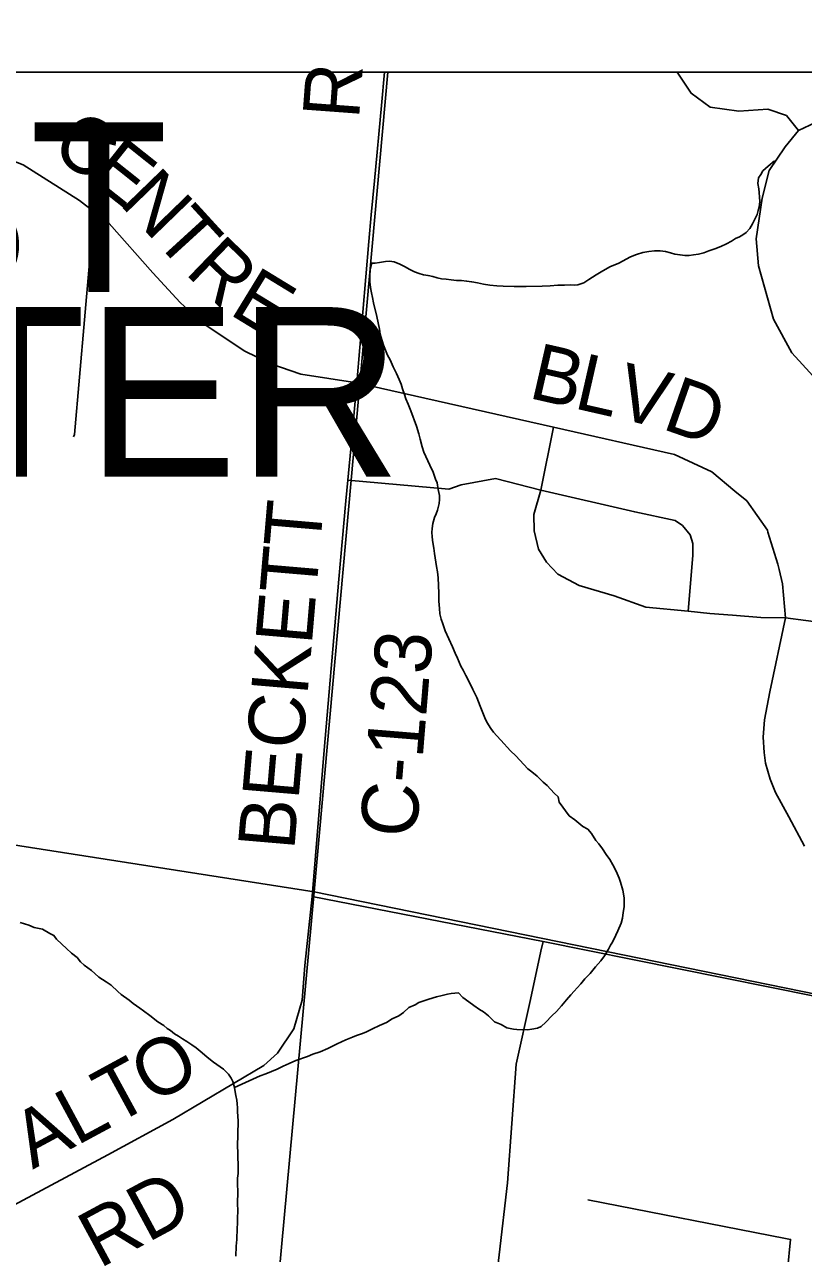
# Model space of a CAD drawing. Extents: x 0 to 34, y 0 to 22.
# Drawn here: x 5.283 to 6.065, y 16.973 to 18.207 of the extents above; entities that cross this region are included whole.
import ezdxf

# ---------------------------------------------------------------- set-up
doc = ezdxf.new("R2010")
doc.units = 0
for name, color, linetype in [('GM_X_County_Road', 7, 'Continuous'), ('GM_X_County_Road_Text', 7, 'Continuous'), ('GM_X_Minor_River', 7, 'Continuous'), ('GM_X_Section', 7, 'Continuous'), ('GM_X_Township_Road', 7, 'Continuous'), ('GM_X_Township_Road_Text', 7, 'Continuous'), ('GM_X_Township_Text', 7, 'Continuous'), ('SH_Text', 7, 'Continuous')]:
    doc.layers.add(name, color=color, linetype=linetype)

msp = doc.modelspace()

# ---------------------------------------------------------------- linework, layer by layer
at = {"layer": 'GM_X_County_Road'}
for p, q in [((5.6163, 17.8474), (5.6285, 17.9891)), ((5.6109, 17.788), (5.6163, 17.8474))]:
    msp.add_line(p, q, dxfattribs=at)
for points in [[(4.6846, 18.1624), (4.7517, 18.1578), (4.9233, 18.1379), (5.0879, 18.1139), (5.1086, 18.1108), (5.192, 18.0966), (5.238, 18.0831), (5.2814, 18.0662), (5.3381, 18.0304), (5.3678, 18.0072), (5.4117, 17.9578), (5.4392, 17.9278), (5.4607, 17.9078), (5.5032, 17.8793), (5.5302, 17.8663), (5.5602, 17.8558), (5.6163, 17.8474)], [(5.6341, 18.0503), (5.6413, 18.1257), (5.644, 18.1592)], [(5.6285, 17.9891), (5.6309, 18.0161), (5.6341, 18.0503)], [(5.6163, 17.8474), (5.8138, 17.8027), (5.9354, 17.7752), (5.9728, 17.7578), (5.996, 17.7384), (6.0079, 17.7286), (6.0285, 17.6991), (6.0291, 17.6973)], [(5.6055, 17.7286), (5.6074, 17.7495), (5.6109, 17.788)], [(5.5717, 17.3314), (5.5835, 17.4781), (5.5984, 17.6501), (5.6055, 17.7286)], [(6.0291, 17.6973), (6.0391, 17.6652), (6.0404, 17.6596)], [(6.0404, 17.6596), (6.0438, 17.6454), (6.0466, 17.6112)], [(6.0466, 17.6112), (6.031, 17.5368), (6.0255, 17.5088), (6.0243, 17.4913), (6.0252, 17.476), (6.0267, 17.4651), (6.0312, 17.4491), (6.0366, 17.4357), (6.05, 17.4113), (6.0658, 17.3817)], [(6.0466, 17.6112), (6.0876, 17.6058), (6.1121, 17.5959), (6.1422, 17.5721), (6.2262, 17.4703), (6.4637, 17.327), (6.5163, 17.296), (6.5237, 17.2912)], [(5.5717, 17.3314), (5.8034, 17.2861), (6.0757, 17.231)]]:
    msp.add_lwpolyline(points, dxfattribs=at)
at = {"layer": 'GM_X_Minor_River'}
for points in [[(5.7216, 17.9501), (5.7265, 17.9495), (5.7318, 17.9486), (5.7375, 17.9477), (5.7435, 17.9464), (5.75, 17.9454), (5.7568, 17.9448), (5.7632, 17.9442), (5.7743, 17.9439), (5.7796, 17.9441), (5.7864, 17.9439), (5.8024, 17.9442), (5.8104, 17.9447), (5.818, 17.9452), (5.8249, 17.9454), (5.8309, 17.9456), (5.8347, 17.9455), (5.8382, 17.9457), (5.8443, 17.9478), (5.8493, 17.9511), (5.8567, 17.9558), (5.8617, 17.9587), (5.8702, 17.9638), (5.8795, 17.9673), (5.8911, 17.9738), (5.8972, 17.9763), (5.9034, 17.9783), (5.9095, 17.9793), (5.9152, 17.9799), (5.9209, 17.9797), (5.9262, 17.9792), (5.9311, 17.9779), (5.9356, 17.9766), (5.9409, 17.9757), (5.9455, 17.9752), (5.95, 17.975), (5.9542, 17.9757), (5.9592, 17.9766), (5.9646, 17.978), (5.9699, 17.9797), (5.9757, 17.9818), (5.9818, 17.9843), (5.9876, 17.9868), (5.9926, 17.9897), (5.9965, 17.9922), (6.0004, 17.994), (6.0038, 17.9958), (6.0073, 17.9984), (6.0109, 18.0024), (6.0137, 18.0069), (6.0165, 18.0129), (6.0181, 18.0163), (6.0194, 18.0204), (6.0203, 18.0238), (6.0208, 18.0295), (6.0205, 18.0337), (6.0203, 18.0383), (6.02, 18.0421), (6.019, 18.0474), (6.0196, 18.0531), (6.022, 18.0565), (6.024, 18.0602), (6.0294, 18.065), (6.0357, 18.0701)], [(5.776, 17.4725), (5.7708, 17.4776), (5.7609, 17.4882), (5.7568, 17.4928), (5.7535, 17.4964), (5.7509, 17.4999), (5.747, 17.5064), (5.7448, 17.5107), (5.743, 17.5157), (5.7402, 17.5226), (5.7367, 17.5311), (5.7327, 17.5392), (5.7291, 17.5469), (5.7259, 17.5531), (5.723, 17.5585), (5.7209, 17.5627), (5.7191, 17.5666), (5.7173, 17.5708), (5.7152, 17.5758), (5.7123, 17.582), (5.7052, 17.5982), (5.7027, 17.6051), (5.701, 17.6097), (5.6996, 17.6151), (5.6994, 17.6204), (5.6988, 17.628), (5.6987, 17.636), (5.6982, 17.6436), (5.698, 17.6512), (5.6974, 17.6573), (5.6964, 17.6627), (5.6945, 17.6757), (5.6936, 17.681), (5.6929, 17.6849), (5.6923, 17.6891), (5.692, 17.6929), (5.6917, 17.697), (5.6919, 17.7008), (5.6928, 17.7061), (5.6945, 17.7118), (5.6961, 17.7155), (5.6973, 17.7193), (5.6991, 17.7261), (5.6995, 17.7299), (5.6993, 17.7341), (5.698, 17.7402), (5.697, 17.7467), (5.6952, 17.7505), (5.6931, 17.7574), (5.6895, 17.7644), (5.6838, 17.7775), (5.6821, 17.7829), (5.68, 17.7905), (5.6787, 17.7959), (5.6762, 17.8036), (5.6706, 17.819), (5.6678, 17.8259), (5.6657, 17.8313), (5.6643, 17.8355), (5.6621, 17.8413), (5.6608, 17.8459), (5.659, 17.8505), (5.6561, 17.8566), (5.6529, 17.8632), (5.6497, 17.8705), (5.6472, 17.8752), (5.6451, 17.8802), (5.6433, 17.8852), (5.6419, 17.8894), (5.6398, 17.8963), (5.6392, 17.9013), (5.6379, 17.9074), (5.6365, 17.9139), (5.6331, 17.9277), (5.6322, 17.933), (5.6312, 17.9376), (5.6305, 17.9411), (5.6299, 17.9456), (5.6296, 17.9491), (5.6294, 17.9548), (5.6299, 17.9608), (5.6313, 17.9673), (5.6347, 17.9675), (5.6393, 17.9682), (5.645, 17.9691), (5.6492, 17.9694), (5.6537, 17.9689), (5.6594, 17.9664), (5.6642, 17.964), (5.6695, 17.9612), (5.6743, 17.9587), (5.6789, 17.9571), (5.6834, 17.9558), (5.6879, 17.9549), (5.6928, 17.954), (5.697, 17.9527), (5.7015, 17.9518), (5.7061, 17.9513), (5.711, 17.9508), (5.7163, 17.9502), (5.7216, 17.9501)], [(5.4937, 17.1393), (5.5195, 17.1511), (5.5249, 17.1532), (5.5306, 17.1553), (5.5364, 17.1578), (5.5426, 17.1607), (5.5484, 17.1635), (5.5553, 17.1664), (5.5668, 17.1706), (5.5722, 17.1727), (5.5795, 17.1751), (5.5872, 17.1787), (5.5968, 17.1833), (5.6053, 17.1873), (5.6122, 17.1901), (5.6161, 17.1915), (5.6211, 17.1933), (5.6253, 17.195), (5.6322, 17.1982), (5.6392, 17.2018), (5.6461, 17.2047), (5.6519, 17.2083), (5.6585, 17.2115), (5.6631, 17.2148), (5.6686, 17.2196), (5.6748, 17.2224), (5.6786, 17.2246), (5.6886, 17.2281), (5.6963, 17.2305), (5.702, 17.2318), (5.7074, 17.2332), (5.7112, 17.2338), (5.7146, 17.2341), (5.7184, 17.2344), (5.7229, 17.2297), (5.7288, 17.2253), (5.734, 17.2217), (5.7396, 17.2178), (5.7437, 17.2154), (5.7486, 17.2114), (5.7545, 17.2055), (5.7612, 17.2027), (5.7668, 17.1994), (5.7736, 17.1981), (5.777, 17.1976), (5.7877, 17.1973), (5.7919, 17.1979), (5.7976, 17.1989), (5.8015, 17.2007), (5.8061, 17.2051), (5.812, 17.2114), (5.8167, 17.2158), (5.8218, 17.2213), (5.827, 17.2276), (5.8313, 17.2325), (5.8344, 17.2362), (5.8376, 17.2395), (5.8411, 17.2436), (5.8454, 17.2484), (5.8505, 17.2539), (5.856, 17.2606), (5.8612, 17.2665), (5.8651, 17.2717), (5.8691, 17.2784), (5.8711, 17.2822), (5.8731, 17.2855), (5.8764, 17.2923), (5.8784, 17.2968), (5.8817, 17.3043), (5.883, 17.3096), (5.8839, 17.3152), (5.8848, 17.3209), (5.8849, 17.3251), (5.8847, 17.3297), (5.884, 17.3339), (5.8834, 17.3377), (5.881, 17.3457), (5.8796, 17.3496), (5.8778, 17.3542), (5.8757, 17.3588), (5.8735, 17.3631), (5.8702, 17.3685), (5.8666, 17.3735), (5.8629, 17.379), (5.8593, 17.384), (5.8564, 17.3875), (5.852, 17.3945), (5.8483, 17.3988), (5.8431, 17.4016), (5.8353, 17.4083), (5.8297, 17.4123), (5.8195, 17.4259), (5.8185, 17.4313), (5.8144, 17.4352), (5.8074, 17.4426), (5.8033, 17.4462), (5.7974, 17.4521), (5.7919, 17.4564), (5.7881, 17.4596), (5.78, 17.4682), (5.776, 17.4725)], [(5.4948, 16.97), (5.4953, 16.9799), (5.4959, 16.9867), (5.4959, 16.9901), (5.4964, 16.9947), (5.4969, 17.0175), (5.4966, 17.0209), (5.4969, 17.0365), (5.4966, 17.0407), (5.4967, 17.0445), (5.4967, 17.0483), (5.4972, 17.0529), (5.4974, 17.0628), (5.4968, 17.0685), (5.4969, 17.0746), (5.4966, 17.0799), (5.4971, 17.1054), (5.4966, 17.1153), (5.4967, 17.1191), (5.4964, 17.1229), (5.496, 17.1267), (5.495, 17.1313), (5.4943, 17.1351), (5.4937, 17.1393), (5.4919, 17.1454), (5.4901, 17.1489), (5.4875, 17.1527), (5.4827, 17.1578), (5.4726, 17.1648), (5.4663, 17.1699), (5.4611, 17.1742), (5.4551, 17.1793), (5.4507, 17.1824), (5.4458, 17.1855), (5.4413, 17.1883), (5.4372, 17.191), (5.4335, 17.1934), (5.4294, 17.1965), (5.426, 17.1985), (5.4227, 17.2016), (5.4167, 17.2055), (5.4085, 17.2118), (5.4022, 17.2165), (5.3985, 17.2189), (5.3918, 17.2236), (5.3877, 17.2271), (5.3799, 17.2329), (5.3765, 17.2357), (5.3698, 17.2423), (5.3646, 17.2454), (5.3575, 17.2501), (5.3534, 17.254), (5.3501, 17.2568), (5.3426, 17.2622), (5.3389, 17.2657), (5.3356, 17.27), (5.33, 17.2743), (5.3248, 17.279), (5.3204, 17.2832), (5.3148, 17.2883), (5.3123, 17.2922), (5.3081, 17.2941), (5.301, 17.2985), (5.2924, 17.3002), (5.2871, 17.3026), (5.2785, 17.305)]]:
    msp.add_lwpolyline(points, dxfattribs=at)
at = {"layer": 'GM_X_Section'}
for points in [[(5.6474, 18.1592), (5.5736, 17.336), (4.5906, 17.4897), (4.6831, 18.5192), (5.1102, 18.4472)], [(6.5636, 18.1592), (6.6692, 18.1363), (6.585, 17.1294), (5.5736, 17.336), (5.6474, 18.1592)], [(4.8773, 16.3947), (4.4981, 16.447), (4.5906, 17.4897), (5.5736, 17.336), (5.489, 16.4145)], [(5.489, 16.4145), (5.5736, 17.336), (6.585, 17.1294), (6.5225, 16.4145)]]:
    msp.add_lwpolyline(points, dxfattribs=at)
at = {"layer": 'GM_X_Township_Road'}
for p, q in [((5.8012, 17.2763), (5.8034, 17.2861)), ((5.7906, 17.2278), (5.8012, 17.2763)), ((6.0466, 16.9877), (5.8483, 17.0266))]:
    msp.add_line(p, q, dxfattribs=at)
for points in [[(6.0597, 18.1006), (6.0476, 18.1158), (6.0288, 18.1223), (5.9997, 18.12), (5.9711, 18.1242), (5.9519, 18.1381), (5.9379, 18.1592)], [(6.0815, 17.8463), (6.0531, 17.8775), (6.0348, 17.9113), (6.0196, 17.9648), (6.0172, 17.992), (6.0233, 18.0327), (6.0303, 18.0605), (6.0463, 18.0843), (6.0597, 18.1006), (6.1111, 18.1247)], [(5.3319, 17.7931), (5.3328, 17.7952), (5.3479, 17.968), (5.3481, 17.9695), (5.3486, 17.9725), (5.3492, 17.9752), (5.3499, 17.9779), (5.3506, 17.9802), (5.3515, 17.9825), (5.3525, 17.9851), (5.3537, 17.9876), (5.355, 17.9904), (5.3563, 17.9925), (5.3579, 17.9951), (5.3592, 17.9971), (5.3614, 17.9999), (5.3641, 18.0031), (5.3678, 18.0072)], [(5.8138, 17.8027), (5.8012, 17.7395), (5.7939, 17.7151), (5.7944, 17.6985), (5.7987, 17.6802), (5.8069, 17.6672), (5.8183, 17.655), (5.8395, 17.6435), (5.8746, 17.6332), (5.9064, 17.6218), (5.9489, 17.618), (5.9709, 17.6155), (5.9935, 17.6139), (6.022, 17.6115), (6.0466, 17.6112)], [(5.6074, 17.7495), (5.7089, 17.7405), (5.721, 17.7447), (5.7556, 17.751), (5.8012, 17.7395), (5.8953, 17.7175), (5.9358, 17.7088), (5.9434, 17.7039), (5.951, 17.6947), (5.9538, 17.6857), (5.9538, 17.6737), (5.9489, 17.618)], [(5.1782, 16.9728), (5.2241, 16.9957), (5.3665, 17.0716), (5.4316, 17.1072), (5.5229, 17.1614), (5.5369, 17.1739), (5.5533, 17.1982), (5.5614, 17.2271), (5.5641, 17.262), (5.5717, 17.3314)], [(5.9884, 16.7109), (5.9765, 16.7119), (5.7564, 16.761), (5.7473, 16.7687), (5.7375, 16.7841), (5.7319, 16.8114), (5.7389, 16.8486), (5.7508, 16.8991), (5.7676, 17.0435), (5.7764, 17.1627), (5.7906, 17.2278)], [(6.062, 16.8517), (6.0504, 16.8591), (6.0441, 16.8679), (6.0424, 16.8798), (6.0427, 16.8942), (6.0518, 16.9867), (6.0466, 16.9877)]]:
    msp.add_lwpolyline(points, dxfattribs=at)
at = {"layer": 'SH_Text'}
msp.add_lwpolyline([(8.8041, 18.7255), (5.1102, 18.7255), (5.1102, 18.1592), (8.8041, 18.1592)], close=True, dxfattribs=at)

# ---------------------------------------------------------------- texts
at = {"layer": 'GM_X_County_Road_Text'}
for s, height, rotation, p in [('R', 0.0568, 85.781, (5.6185, 18.1114)), ('C', 0.0568, 326.3451, (5.3071, 18.0777)), ('E', 0.0568, 321.4684, (5.3449, 18.0526)), ('N', 0.0568, 314.1319, (5.3767, 18.0274)), ('T', 0.0568, 312.4021, (5.4112, 17.9919)), ('R', 0.0568, 316.09, (5.4427, 17.9576)), ('E', 0.0568, 328.5964, (5.487, 17.917)), ('B', 0.0568, 347.1414, (5.7874, 17.8324)), ('L', 0.0568, 347.1442, (5.8329, 17.822)), ('V', 0.0568, 346.6657, (5.8742, 17.8126)), ('D', 0.0568, 340.6521, (5.9214, 17.8015)), ('BECKETT', 0.05682, 85.1213, (5.5535, 17.377)), ('C-123', 0.05682, 85.3275, (5.6759, 17.3892))]:
    msp.add_text(s, height=height, rotation=rotation, dxfattribs=at).set_placement(p)
at = {"layer": 'GM_X_Township_Road_Text'}
for s, height, rotation, p in [('O', 0.0568, 29.8613, (5.4111, 17.1218)), ('T', 0.0568, 28.5807, (5.3726, 17.1008)), ('L', 0.0568, 28.3353, (5.335, 17.0805)), ('A', 0.0568, 28.3296, (5.291, 17.0568)), ('RD', 0.05682, 28.3345, (5.358, 16.9571))]:
    msp.add_text(s, height=height, rotation=rotation, dxfattribs=at).set_placement(p)
at = {"layer": 'GM_X_Township_Text'}
for s, p in [('WEST', (4.7686, 17.9384)), ('CHESTER', (4.572, 17.7529))]:
    msp.add_text(s, height=0.17045, rotation=0, dxfattribs=at).set_placement(p)

doc.saveas('drawing.dxf')
